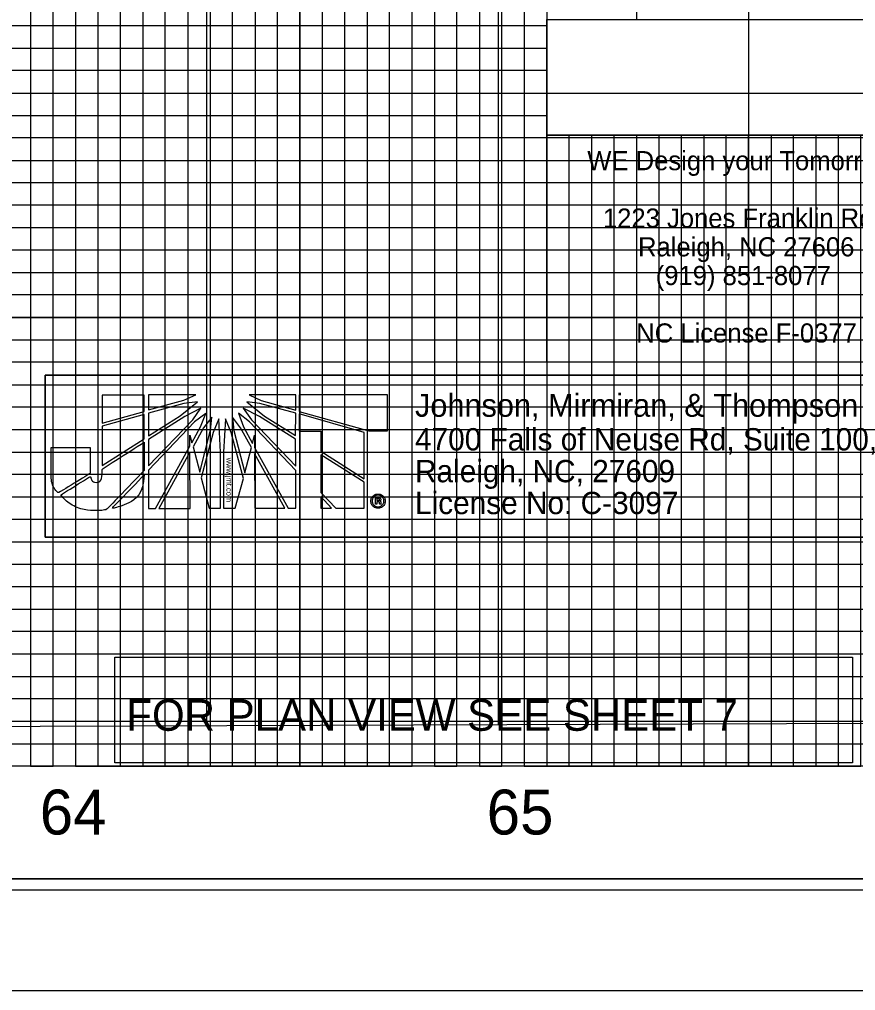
# Model space of a CAD drawing. Extents: x 557032 to 562069, y 513430 to 515874.
# Drawn here: x 558437 to 558623.3, y 514774.3 to 514990.7 of the extents above; entities that cross this region are included whole.
import ezdxf

# ---------------------------------------------------------------- set-up
doc = ezdxf.new("R2010")
doc.units = 0
for name, color, linetype in [('Exist Vertical Profile Horizontal Axis Label Major', 7, 'Continuous'), ('Prop DSN Text', 7, 'Continuous'), ('Prop VPI Label', 7, 'Continuous'), ('Scratch_Level_5', 7, 'Continuous'), ('Sheet Cutting Line CELL', 7, 'Continuous'), ('Sheet DOT Grid CELL', 7, 'Continuous'), ('Sheet Layout Profile Border Port 2', 7, 'Continuous'), ('Sheet Plot Border Inside CELL', 7, 'Continuous'), ('Sheet Plot Border Outside CELL', 7, 'Continuous'), ('Sheet Profile CELL', 7, 'Continuous'), ('Sheet Profile Grid Major CELL', 7, 'Continuous'), ('Sheet Profile Grid Middle CELL', 7, 'Continuous'), ('Sheet Profile Grid Minor CELL', 7, 'Continuous')]:
    doc.layers.add(name, color=color, linetype=linetype)

msp = doc.modelspace()

# ---------------------------------------------------------------- linework, layer by layer
at = {"layer": 'Prop DSN Text'}
for p, q in [((558554.45, 514990.68), (558639.79, 514990.68)), ((558554.45, 514914.28), (558554.45, 514990.68)), ((558639.79, 514964.88), (558554.45, 514964.88)), ((558639.79, 514914.28), (558554.45, 514914.28))]:
    msp.add_line(p, q, dxfattribs=at)
at = {"layer": 'Prop VPI Label'}
for p, q in [((558464.74, 514906.97), (558455.38, 514906.96)), ((558455.38, 514906.96), (558455.38, 514900.75)), ((558464.74, 514903.35), (558464.74, 514906.97)), ((558476.25, 514907.02), (558465.71, 514907.01)), ((558465.71, 514907.01), (558465.71, 514903.66)), ((558473.56, 514905.83), (558476.25, 514907.02)), ((558498.55, 514907), (558488.17, 514907.03)), ((558488.17, 514907.03), (558490.8, 514905.8)), ((558498.56, 514903.63), (558498.55, 514907)), ((558518.96, 514907.06), (558499.28, 514907.05)), ((558499.28, 514907.05), (558499.28, 514903.43)), ((558518.97, 514899), (558518.96, 514907.06)), ((558465.71, 514903.66), (558473.56, 514905.83)), ((558473.56, 514905.11), (558465.72, 514902.94)), ((558472.74, 514902.32), (558476.62, 514905.48)), ((558476.62, 514905.48), (558473.56, 514905.11)), ((558477.39, 514904.03), (558473.83, 514902.22)), ((558475.59, 514901.49), (558477.39, 514904.03)), ((558486.83, 514904.04), (558488.64, 514901.46)), ((558490.45, 514902.23), (558486.83, 514904.04)), ((558487.65, 514905.49), (558491.58, 514902.28)), ((558490.54, 514905.12), (558487.65, 514905.49)), ((558498.56, 514902.92), (558490.54, 514905.12)), ((558490.8, 514905.8), (558498.56, 514903.63)), ((558455.38, 514900.75), (558464.74, 514903.35)), ((558464.74, 514902.67), (558455.38, 514900.04)), ((558464.75, 514897.25), (558464.74, 514902.67)), ((558465.72, 514902.94), (558465.72, 514897.87)), ((558465.72, 514897.87), (558472.74, 514902.32)), ((558473.83, 514902.22), (558465.72, 514897.05)), ((558478.48, 514902.9), (558475.99, 514900.98)), ((558477.33, 514899.9), (558478.48, 514902.9)), ((558479.82, 514902.07), (558477.97, 514899.69)), ((558479.56, 514899.18), (558479.82, 514902.07)), ((558484.41, 514902.07), (558484.72, 514899.08)), ((558486.22, 514899.7), (558484.41, 514902.07)), ((558485.74, 514902.91), (558486.88, 514899.91)), ((558488.22, 514900.99), (558485.74, 514902.91)), ((558498.5, 514897.13), (558490.45, 514902.23)), ((558491.58, 514902.28), (558498.5, 514897.96)), ((558498.5, 514897.96), (558498.56, 514902.92)), ((558499.28, 514903.43), (558499.28, 514903.32)), ((558499.28, 514903.32), (558514.78, 514899)), ((558499.28, 514902.77), (558499.28, 514902.7)), ((558513.79, 514898.64), (558499.28, 514902.77)), ((558499.28, 514902.7), (558499.29, 514898.94)), ((558455.38, 514900.04), (558455.39, 514891.31)), ((558465.73, 514891.21), (558475.59, 514901.49)), ((558475.99, 514900.98), (558465.73, 514890.22)), ((558475.38, 514896.33), (558477.33, 514899.9)), ((558477.97, 514899.69), (558475.64, 514895.45)), ((558481.36, 514901.65), (558480.09, 514898.65)), ((558481.77, 514894.27), (558481.36, 514901.65)), ((558482.91, 514901.65), (558482.44, 514894.27)), ((558484.15, 514898.66), (558482.91, 514901.65)), ((558488.65, 514895.31), (558486.22, 514899.7)), ((558486.88, 514899.91), (558488.89, 514896.19)), ((558498.51, 514890.16), (558488.22, 514900.99)), ((558488.64, 514901.46), (558498.51, 514891.13)), ((558474.91, 514895.56), (558474.91, 514898.03)), ((558474.91, 514898.03), (558475.38, 514896.33)), ((558477.14, 514889.83), (558479.56, 514899.18)), ((558480.09, 514898.65), (558477.45, 514888.53)), ((558486.85, 514888.39), (558484.15, 514898.66)), ((558484.72, 514899.08), (558487.15, 514889.62)), ((558488.89, 514896.19), (558489.37, 514898.05)), ((558489.37, 514898.05), (558489.37, 514895.31)), ((558499.29, 514898.94), (558504.09, 514898.94)), ((558504.09, 514898.94), (558504.1, 514894.44)), ((558513.8, 514888.31), (558513.79, 514898.64)), ((558514.78, 514899), (558518.97, 514899)), ((558455.39, 514891.31), (558464.75, 514897.25)), ((558465.72, 514897.05), (558465.73, 514891.21)), ((558467.28, 514881.73), (558474.91, 514895.56)), ((558475.64, 514895.45), (558477.14, 514889.83)), ((558487.15, 514889.62), (558488.65, 514895.31)), ((558489.37, 514895.31), (558496.86, 514881.76)), ((558498.51, 514891.13), (558498.5, 514897.13)), ((558474.91, 514894.22), (558468.01, 514881.73)), ((558474.99, 514881.73), (558474.91, 514894.22)), ((558481.79, 514881.79), (558481.77, 514894.27)), ((558482.44, 514894.27), (558482.45, 514881.79)), ((558496.09, 514881.8), (558489.37, 514893.97)), ((558489.37, 514893.97), (558489.39, 514881.79)), ((558504.1, 514894.44), (558513.8, 514888.31)), ((558504.1, 514893.67), (558504.1, 514885.3)), ((558513.8, 514887.58), (558504.1, 514893.67)), ((558465.73, 514890.22), (558465.74, 514881.73)), ((558498.52, 514881.76), (558498.51, 514890.16)), ((558477.45, 514888.53), (558479.22, 514881.78)), ((558485.05, 514881.79), (558486.85, 514888.39)), ((558513.81, 514881.77), (558513.8, 514887.58)), ((558504.1, 514885.3), (558507.46, 514881.77)), ((558516.86, 514884.93), (558516.86, 514884.64)), ((558516.86, 514884.64), (558516.86, 514884.93)), ((558506.53, 514881.76), (558504.1, 514884.39)), ((558504.1, 514884.39), (558504.11, 514881.76)), ((558516.27, 514882.66), (558516.27, 514884.09)), ((558516.27, 514884.09), (558516.86, 514884.09)), ((558516.6, 514882.66), (558516.27, 514882.66)), ((558516.86, 514883.82), (558516.6, 514883.82)), ((558516.6, 514883.82), (558516.6, 514883.48)), ((558516.6, 514883.48), (558516.86, 514883.48)), ((558516.86, 514883.22), (558516.6, 514883.22)), ((558516.6, 514883.22), (558516.6, 514882.66)), ((558516.86, 514884.09), (558516.86, 514883.82)), ((558516.86, 514883.82), (558516.86, 514884.09)), ((558516.86, 514884.09), (558516.95, 514884.09)), ((558516.9, 514883.82), (558516.86, 514883.82)), ((558516.86, 514883.48), (558516.86, 514883.22)), ((558516.86, 514883.22), (558516.86, 514883.48)), ((558516.86, 514883.48), (558516.87, 514883.48)), ((558516.87, 514883.22), (558516.86, 514883.22)), ((558465.74, 514881.73), (558467.28, 514881.73)), ((558468.01, 514881.73), (558474.99, 514881.73)), ((558479.22, 514881.78), (558481.79, 514881.79)), ((558482.45, 514881.79), (558485.05, 514881.79)), ((558489.39, 514881.79), (558496.09, 514881.8)), ((558496.86, 514881.76), (558498.52, 514881.76)), ((558504.11, 514881.76), (558506.53, 514881.76)), ((558507.46, 514881.77), (558513.81, 514881.77)), ((558516.86, 514882.1), (558516.86, 514881.79)), ((558516.86, 514881.79), (558516.86, 514882.1)), ((558516.86, 514882.1), (558516.87, 514882.1)), ((558516.87, 514881.79), (558516.86, 514881.79))]:
    msp.add_line(p, q, dxfattribs=at)
for points in [[(558554.45, 514964.88), (558639.79, 514964.88), (558639.79, 514914.28), (558554.45, 514914.28)], [(558442.72, 514911.39), (558642.75, 514911.39), (558642.75, 514875.29), (558442.72, 514875.29)], [(558442.72, 514875.29), (558642.75, 514875.29), (558642.75, 514911.39), (558442.72, 514911.39)], [(558458.18, 514848.55), (558622.6, 514848.55), (558622.6, 514825.04), (558458.18, 514825.04)], [(558458.18, 514848.55), (558622.6, 514848.55), (558622.6, 514825.04), (558458.18, 514825.04)]]:
    msp.add_lwpolyline(points, close=True, dxfattribs=at)
for points in [[(558455.38, 514900.75), (558464.74, 514903.35), (558464.74, 514906.97), (558455.38, 514906.96), (558455.38, 514900.75)], [(558473.56, 514905.83), (558476.25, 514907.02), (558465.71, 514907.01), (558465.71, 514903.66), (558473.56, 514905.83)], [(558490.8, 514905.8), (558498.56, 514903.63), (558498.55, 514907), (558488.17, 514907.03), (558490.8, 514905.8)], [(558518.96, 514907.06), (558499.28, 514907.05), (558499.28, 514903.43), (558499.28, 514903.32), (558514.78, 514899), (558518.97, 514899), (558518.96, 514907.06)], [(558465.72, 514902.94), (558465.72, 514897.87), (558472.74, 514902.32), (558476.62, 514905.48), (558473.56, 514905.11), (558465.72, 514902.94)], [(558465.72, 514897.05), (558465.73, 514891.21), (558475.59, 514901.49), (558477.39, 514904.03), (558473.83, 514902.22), (558465.72, 514897.05)], [(558486.83, 514904.04), (558488.64, 514901.46), (558498.51, 514891.13), (558498.5, 514897.13), (558490.45, 514902.23), (558486.83, 514904.04)], [(558487.65, 514905.49), (558491.58, 514902.28), (558498.5, 514897.96), (558498.56, 514902.92), (558490.54, 514905.12), (558487.65, 514905.49)], [(558455.39, 514891.31), (558464.75, 514897.25), (558464.74, 514902.67), (558455.38, 514900.04), (558455.39, 514891.31)], [(558478.48, 514902.9), (558475.99, 514900.98), (558465.73, 514890.22), (558465.74, 514881.73), (558467.28, 514881.73), (558474.91, 514895.56), (558474.91, 514898.03), (558475.38, 514896.33), (558477.33, 514899.9), (558478.48, 514902.9)], [(558479.82, 514902.07), (558477.97, 514899.69), (558475.64, 514895.45), (558477.14, 514889.83), (558479.56, 514899.18), (558479.82, 514902.07)], [(558484.41, 514902.07), (558484.72, 514899.08), (558487.15, 514889.62), (558488.65, 514895.31), (558486.22, 514899.7), (558484.41, 514902.07)], [(558485.74, 514902.91), (558486.88, 514899.91), (558488.89, 514896.19), (558489.37, 514898.05), (558489.37, 514895.31), (558496.86, 514881.76), (558498.52, 514881.76), (558498.51, 514890.16), (558488.22, 514900.99), (558485.74, 514902.91)], [(558499.28, 514902.77), (558499.28, 514902.7), (558499.29, 514898.94), (558504.09, 514898.94), (558504.1, 514894.44), (558513.8, 514888.31), (558513.79, 514898.64), (558499.28, 514902.77)], [(558480.09, 514898.65), (558477.45, 514888.53), (558479.22, 514881.78), (558481.79, 514881.79), (558481.77, 514894.27), (558481.36, 514901.65), (558480.09, 514898.65)], [(558482.91, 514901.65), (558482.44, 514894.27), (558482.45, 514881.79), (558485.05, 514881.79), (558486.85, 514888.39), (558484.15, 514898.66), (558482.91, 514901.65)], [(558468.01, 514881.73), (558474.99, 514881.73), (558474.91, 514894.22), (558468.01, 514881.73)], [(558489.39, 514881.79), (558496.09, 514881.8), (558489.37, 514893.97), (558489.39, 514881.79)], [(558504.1, 514893.67), (558504.1, 514885.3), (558507.46, 514881.77), (558513.81, 514881.77), (558513.8, 514887.58), (558504.1, 514893.67), (558504.1, 514893.67)], [(558504.11, 514881.76), (558504.11, 514881.76), (558506.53, 514881.76), (558504.1, 514884.39), (558504.11, 514881.76)], [(558517.48, 514883), (558517.48, 514882.92), (558517.5, 514882.87), (558517.5, 514882.81), (558517.53, 514882.66), (558517.24, 514882.66)]]:
    msp.add_lwpolyline(points, dxfattribs=at)
for points, degree in [([(558452.7, 514895.32), (558452.7, 514895.32), (558444.03, 514895.31), (558444.03, 514895.31), (558444.03, 514895.31), (558444.04, 514889.89), (558444.04, 514889.89), (558444.04, 514889.89), (558444.04, 514889.32), (558444.04, 514889.32), (558444.04, 514887.62), (558444.6, 514886.28), (558445.59, 514885.15), (558445.59, 514885.15), (558452.71, 514889.48), (558452.71, 514889.59), (558452.71, 514889.59), (558452.7, 514895.32), (558452.7, 514895.32)], 3), ([(558454.05, 514887.52), (558453.5, 514887.52), (558453.02, 514887.83), (558452.81, 514888.87), (558452.81, 514888.87), (558446.1, 514884.7), (558446.1, 514884.7), (558448.17, 514882.53), (558451.48, 514881.23), (558454.27, 514881.24), (558455, 514881.24), (558455.56, 514881.3), (558456.33, 514881.45), (558456.33, 514881.45), (558464.75, 514890.17), (558464.75, 514890.17), (558464.75, 514890.17), (558464.75, 514896.48), (558464.75, 514896.48), (558464.75, 514896.48), (558455.39, 514890.52), (558455.39, 514890.52), (558455.4, 514888.16), (558454.82, 514887.52), (558454.05, 514887.52)], 3), ([(558454.05, 514887.52), (558453.5, 514887.52), (558453.02, 514887.83), (558452.81, 514888.87), (558452.81, 514888.87), (558446.1, 514884.7), (558446.1, 514884.7), (558448.17, 514882.53), (558451.48, 514881.23), (558454.27, 514881.24), (558455, 514881.24), (558455.56, 514881.3), (558456.33, 514881.45), (558456.33, 514881.45), (558464.75, 514890.17), (558464.75, 514890.17), (558464.75, 514890.17), (558464.75, 514896.48), (558464.75, 514896.48), (558464.75, 514896.48), (558455.39, 514890.52), (558455.39, 514890.52), (558455.4, 514888.16), (558454.82, 514887.52), (558454.05, 514887.52)], 3), ([(558464.76, 514889.19), (558464.76, 514889.19), (558457.47, 514881.66), (558457.47, 514881.66), (558461.04, 514882.54), (558464.59, 514884.91), (558464.76, 514889.19)], 3), ([(558516.86, 514881.79), (558516.43, 514881.79), (558516.05, 514881.94), (558515.74, 514882.25), (558515.43, 514882.55), (558515.27, 514882.93), (558515.27, 514883.37), (558515.27, 514883.81), (558515.43, 514884.19), (558515.74, 514884.48), (558516.05, 514884.78), (558516.41, 514884.93), (558516.86, 514884.93)], 3), ([(558516.86, 514884.64), (558516.5, 514884.64), (558516.21, 514884.52), (558515.96, 514884.28), (558515.71, 514884.04), (558515.58, 514883.72), (558515.58, 514883.37), (558515.58, 514883.02), (558515.71, 514882.71), (558515.96, 514882.46), (558516.21, 514882.22), (558516.51, 514882.1), (558516.86, 514882.1)], 3), ([(558516.86, 514884.93), (558517.3, 514884.94), (558517.68, 514884.78), (558517.99, 514884.48), (558518.3, 514884.19), (558518.46, 514883.82), (558518.46, 514883.38)], 3), ([(558516.87, 514882.1), (558517.22, 514882.1), (558517.52, 514882.22), (558517.77, 514882.46), (558518.02, 514882.71), (558518.15, 514883.02), (558518.15, 514883.37), (558518.15, 514883.73), (558518.01, 514884.04), (558517.77, 514884.29), (558517.52, 514884.52), (558517.22, 514884.64), (558516.86, 514884.64)], 3), ([(558516.87, 514883.48), (558517.08, 514883.48), (558517.18, 514883.54), (558517.18, 514883.66), (558517.18, 514883.76), (558517.09, 514883.82), (558516.9, 514883.82)], 3), ([(558518.46, 514883.38), (558518.46, 514882.93), (558518.3, 514882.56), (558518, 514882.24), (558517.69, 514881.94), (558517.31, 514881.79), (558516.87, 514881.79)], 3), ([(558517.12, 514883.17), (558517.08, 514883.19), (558517, 514883.22), (558516.87, 514883.22)], 2), ([(558516.95, 514884.09), (558517.31, 514884.09), (558517.49, 514883.95), (558517.49, 514883.66), (558517.49, 514883.53), (558517.44, 514883.43), (558517.33, 514883.35)], 3), ([(558517.24, 514882.66), (558517.2, 514882.74), (558517.17, 514882.81), (558517.17, 514882.92), (558517.17, 514883.05), (558517.16, 514883.13), (558517.12, 514883.17)], 3), ([(558517.33, 514883.35), (558517.42, 514883.3), (558517.47, 514883.18), (558517.48, 514883)], 2)]:
    msp.add_open_spline(points, degree=degree, dxfattribs=at)
at = {"layer": 'Scratch_Level_5'}
for p, q in [((558543.74, 514833.56), (558543.74, 515319.24)), ((558478.73, 514833.32), (558478.73, 515300.8))]:
    msp.add_line(p, q, dxfattribs=at)
msp.add_lwpolyline([(557249.45, 515324.28), (557249.45, 514824.28), (557239, 514812.71), (557236.95, 514799.28), (558647.93, 514799.13), (558699.45, 514799.28), (558649.45, 514824.28), (558649.45, 515324.28)], close=True, dxfattribs=at)
msp.add_lwpolyline([(557250.22, 514849.46), (558648.7, 514849.31), (558650.22, 514849.32)], dxfattribs=at)
at = {"layer": 'Sheet Cutting Line CELL'}
msp.add_line((557032.45, 514774.28), (558716.45, 514774.28), dxfattribs=at)
at = {"layer": 'Sheet DOT Grid CELL'}
for p, q in [((558449.45, 515324.28), (558449.45, 514824.28)), ((558499.45, 515324.28), (558499.45, 514824.28)), ((558549.45, 515324.28), (558549.45, 514824.28)), ((558599.45, 515324.28), (558599.45, 514824.28)), ((557199.45, 514974.28), (558699.34, 514974.28)), ((557199.45, 514924.28), (558699.34, 514924.28)), ((557199.45, 514874.28), (558699.34, 514874.28))]:
    msp.add_line(p, q, dxfattribs=at)
at = {"layer": 'Sheet Layout Profile Border Port 2'}
msp.add_lwpolyline([(557249.45, 515324.28), (558649.45, 515324.28), (558649.45, 514824.28), (557249.45, 514824.28)], close=True, dxfattribs=at)
msp.add_lwpolyline([(557249.45, 514831.1), (558358.41, 514832.88), (558649.45, 514833.95)], dxfattribs=at)
at = {"layer": 'Sheet Plot Border Inside CELL'}
msp.add_lwpolyline([(557045.45, 514796.73), (558711.95, 514796.73), (558711.95, 515851.83), (557045.45, 515851.83)], close=True, dxfattribs=at)
at = {"layer": 'Sheet Plot Border Outside CELL'}
msp.add_lwpolyline([(557032.45, 514774.28), (558716.45, 514774.28), (558716.45, 515874.28), (557032.45, 515874.28)], close=True, dxfattribs=at)
at = {"layer": 'Sheet Profile CELL'}
for p, q in [((558699.45, 514824.28), (557199.45, 514824.28)), ((557199.45, 514799.28), (558699.45, 514799.28))]:
    msp.add_line(p, q, dxfattribs=at)
msp.add_lwpolyline([(558699.45, 515849.28), (557199.45, 515849.28), (557199.45, 514799.28), (558699.45, 514799.28)], close=True, dxfattribs=at)
at = {"layer": 'Sheet Profile Grid Major CELL'}
msp.add_line((558599.45, 514824.28), (558599.45, 514824.28), dxfattribs=at)
for points in [[(558149.45, 514824.28), (558199.45, 514824.28), (558199.45, 515324.28), (558249.45, 515324.28), (558249.45, 514824.28), (558299.45, 514824.28), (558299.45, 515324.28), (558349.45, 515324.28), (558349.45, 514824.28), (558399.45, 514824.28), (558399.45, 515324.28), (558449.45, 515324.28), (558449.45, 514824.28), (558499.45, 514824.28), (558499.45, 515324.28), (558549.45, 515324.28), (558549.45, 514824.28), (558599.45, 514824.28), (558599.45, 514824.28), (558599.45, 514964.88)], [(558699.45, 515024.28), (557199.45, 515024.28), (557199.45, 514974.28), (558554.45, 514974.28)], [(558699.45, 514924.28), (557199.45, 514924.28), (557199.45, 514924.28), (557199.45, 514874.28), (558699.45, 514874.28)], [(558699.45, 514824.28), (557199.45, 514824.28)]]:
    msp.add_lwpolyline(points, dxfattribs=at)
at = {"layer": 'Sheet Profile Grid Middle CELL'}
for points in [[(558174.45, 514824.28), (558224.45, 514824.28), (558224.45, 515324.28), (558274.45, 515324.28), (558274.45, 514824.28), (558324.45, 514824.28), (558324.45, 515324.28), (558374.45, 515324.28), (558374.45, 514824.28), (558424.45, 514824.28), (558424.45, 515324.28), (558474.45, 515324.28), (558474.45, 514824.28), (558524.45, 514824.28), (558524.45, 515324.28), (558574.45, 515324.28), (558574.45, 514990.68)], [(558574.45, 514964.88), (558574.45, 514824.28), (558624.45, 514824.28), (558624.45, 514964.88)], [(558699.45, 514949.28), (557199.45, 514949.28), (557199.45, 514899.28), (558699.45, 514899.28)], [(558699.45, 514849.28), (557199.45, 514849.28)]]:
    msp.add_lwpolyline(points, dxfattribs=at)
at = {"layer": 'Sheet Profile Grid Minor CELL'}
for p, q in [((558554.45, 514989.28), (557249.45, 514989.28)), ((557249.45, 514984.28), (558554.45, 514984.28)), ((558554.45, 514979.28), (557249.45, 514979.28)), ((557249.45, 514969.28), (558554.45, 514969.28)), ((558649.45, 514964.28), (557249.45, 514964.28)), ((557249.45, 514959.28), (558649.45, 514959.28)), ((558649.45, 514954.28), (557249.45, 514954.28)), ((557249.45, 514944.28), (558649.45, 514944.28)), ((558649.45, 514939.28), (557249.45, 514939.28)), ((557249.45, 514934.28), (558649.45, 514934.28)), ((558649.45, 514929.28), (557249.45, 514929.28)), ((557249.45, 514919.28), (558649.45, 514919.28)), ((558649.45, 514914.28), (557249.45, 514914.28)), ((557249.45, 514909.28), (558649.45, 514909.28)), ((558649.45, 514904.28), (557249.45, 514904.28)), ((557249.45, 514894.28), (558649.45, 514894.28)), ((558649.45, 514889.28), (557249.45, 514889.28)), ((557249.45, 514884.28), (558649.45, 514884.28)), ((558649.45, 514879.28), (557249.45, 514879.28)), ((557249.45, 514869.28), (558649.45, 514869.28)), ((558649.45, 514864.28), (557249.45, 514864.28)), ((557249.45, 514859.28), (558649.45, 514859.28)), ((558649.45, 514854.28), (557249.45, 514854.28)), ((557249.45, 514844.28), (558649.45, 514844.28)), ((558649.45, 514839.28), (557249.45, 514839.28)), ((557249.45, 514834.28), (558649.45, 514834.28)), ((557249.45, 514829.28), (558649.45, 514829.28))]:
    msp.add_line(p, q, dxfattribs=at)
for points in [[(558439.45, 515324.28), (558439.45, 514824.28), (558444.45, 514824.28), (558444.45, 515324.28)], [(558454.45, 515324.28), (558454.45, 514824.28), (558459.45, 514824.28), (558459.45, 515324.28)], [(558464.45, 515324.28), (558464.45, 514824.28), (558469.45, 514824.28), (558469.45, 515324.28)], [(558479.45, 515324.28), (558479.45, 514824.28), (558484.45, 514824.28), (558484.45, 515324.28)], [(558489.45, 515324.28), (558489.45, 514824.28), (558494.45, 514824.28), (558494.45, 515324.28)], [(558504.45, 515324.28), (558504.45, 514824.28), (558509.45, 514824.28), (558509.45, 515324.28)], [(558514.45, 515324.28), (558514.45, 514824.28), (558519.45, 514824.28), (558519.45, 515324.28)], [(558529.45, 515324.28), (558529.45, 514824.28), (558534.45, 514824.28), (558534.45, 515324.28)], [(558539.45, 515324.28), (558539.45, 514824.28), (558544.45, 514824.28), (558544.45, 515324.28)], [(558554.45, 515324.28), (558554.45, 514824.28), (558559.45, 514824.28), (558559.45, 514964.88)], [(558564.45, 514964.88), (558564.45, 514824.28), (558569.45, 514824.28), (558569.45, 514964.88)], [(558579.45, 514964.88), (558579.45, 514824.28), (558584.45, 514824.28), (558584.45, 514964.88)], [(558589.45, 514964.88), (558589.45, 514824.28), (558594.45, 514824.28), (558594.45, 514964.88)], [(558604.45, 514964.88), (558604.45, 514824.28), (558609.45, 514824.28), (558609.45, 514964.88)], [(558614.45, 514964.88), (558614.45, 514824.28), (558619.45, 514824.28), (558619.45, 514964.88)]]:
    msp.add_lwpolyline(points, dxfattribs=at)

# ---------------------------------------------------------------- texts
at = {"layer": 'Exist Vertical Profile Horizontal Axis Label Major'}
for s, p in [('64', (558441.49, 514809.06)), ('65', (558541.08, 514809.06))]:
    msp.add_text(s, height=10, dxfattribs=at).set_placement(p)
at = {"layer": 'Prop DSN Text'}
for s, p in [('WE Design your Tomorrow ...', (558563.49, 514957.08)), ('1223 Jones Franklin Road', (558566.98, 514944.28)), ('Raleigh, NC 27606', (558574.8, 514937.88)), ('(919) 851-8077', (558578.74, 514931.48)), ('NC License F-0377', (558574.4, 514918.68))]:
    msp.add_text(s, height=4.2667, rotation=0, dxfattribs=at).set_placement(p)
at = {"layer": 'Prop VPI Label'}
for s, height, p in [('Johnson, Mirmiran, & Thompson Inc.', 5.1112, (558525.1, 514902.14)), ('4700 Falls of Neuse Rd, Suite 100, ', 4.9652, (558525.1, 514894.64)), ('Raleigh, NC, 27609', 4.9652, (558525.1, 514887.55)), ('License No: C-3097', 4.9652, (558525.1, 514880.45)), ('FOR PLAN VIEW SEE SHEET 7', 7, (558460.78, 514832.17))]:
    msp.add_text(s, height=height, dxfattribs=at).set_placement(p)
msp.add_text('www.jmt.com', height=1.2413, rotation=270, dxfattribs=at).set_placement((558483.07, 514893))

doc.saveas('drawing.dxf')
